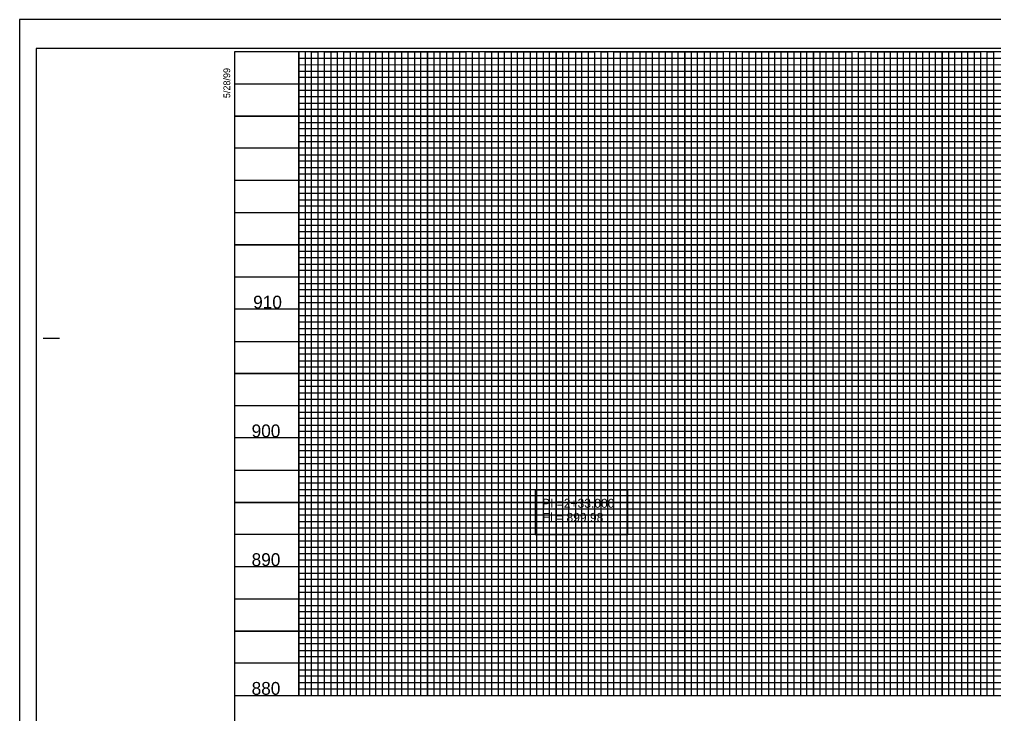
# Model space of a CAD drawing. Extents: x 1648435 to 1651603, y 802691 to 845762.
# Drawn here: x 1648862 to 1649619, y 803252 to 803791 of the extents above; entities that cross this region are included whole.
import ezdxf

# ---------------------------------------------------------------- set-up
doc = ezdxf.new("R2010")
doc.units = 0
for name, color, linetype in [('Exist Vertical Profile Vertical Axis Label', 7, 'Continuous'), ('Prop Grid Mask', 7, 'Continuous'), ('Prop VPI Ditch Grade Right Label', 7, 'Continuous'), ('Sheet Cutting Line CELL', 7, 'Continuous'), ('Sheet DOT Grid CELL', 7, 'Continuous'), ('Sheet Layout Profile Border Port 1', 7, 'Continuous'), ('Sheet Plot Border Inside CELL', 7, 'Continuous'), ('Sheet Plot Border Outside CELL', 7, 'Continuous'), ('Sheet Profile CELL', 7, 'Continuous'), ('Sheet Profile Grid Major CELL', 7, 'Continuous'), ('Sheet Profile Grid Middle CELL', 7, 'Continuous'), ('Sheet Profile Grid Minor CELL', 7, 'Continuous')]:
    doc.layers.add(name, color=color, linetype=linetype)

msp = doc.modelspace()

# ---------------------------------------------------------------- linework, layer by layer
at = {"layer": 'Prop Grid Mask'}
msp.add_lwpolyline([(1649263.05, 803425.57), (1649263.05, 803391.16), (1649335.02, 803391.16), (1649335.02, 803425.57)], close=True, dxfattribs=at)
at = {"layer": 'Sheet Cutting Line CELL'}
for p, q in [((1650546.28, 803791.02), (1648862.28, 803791.02)), ((1648862.28, 803791.02), (1648862.28, 802691.02))]:
    msp.add_line(p, q, dxfattribs=at)
at = {"layer": 'Sheet DOT Grid CELL'}
for p, q in [((1649079.28, 803266.02), (1649079.28, 803766.02)), ((1649129.28, 803266.02), (1649129.28, 803766.02)), ((1649179.28, 803266.02), (1649179.28, 803766.02)), ((1649229.28, 803266.02), (1649229.28, 803766.02)), ((1649279.28, 803266.02), (1649279.28, 803766.02)), ((1649329.28, 803266.02), (1649329.28, 803766.02)), ((1649379.28, 803266.02), (1649379.28, 803766.02)), ((1649429.28, 803266.02), (1649429.28, 803766.02)), ((1649479.28, 803266.02), (1649479.28, 803766.02)), ((1649529.28, 803266.02), (1649529.28, 803766.02)), ((1649579.28, 803266.02), (1649579.28, 803766.02)), ((1650329.23, 803716.02), (1649029.28, 803716.02)), ((1650329.23, 803666.02), (1649029.28, 803666.02)), ((1650329.28, 803616.02), (1649029.28, 803616.02)), ((1650529.28, 803566.02), (1649029.28, 803566.02)), ((1650529.28, 803516.02), (1649029.28, 803516.02)), ((1650529.28, 803466.02), (1649029.28, 803466.02)), ((1650529.28, 803416.02), (1649029.28, 803416.02)), ((1650529.28, 803366.02), (1649029.28, 803366.02)), ((1650529.28, 803316.02), (1649029.28, 803316.02))]:
    msp.add_line(p, q, dxfattribs=at)
at = {"layer": 'Sheet Layout Profile Border Port 1'}
msp.add_lwpolyline([(1649079.28, 803604.97), (1649079.28, 803266.02), (1650479.28, 803266.02), (1650479.28, 803604.97)], dxfattribs=at)
at = {"layer": 'Sheet Plot Border Inside CELL'}
msp.add_lwpolyline([(1648875.28, 802713.47), (1650541.78, 802713.47), (1650541.78, 803768.57), (1648875.28, 803768.57)], close=True, dxfattribs=at)
at = {"layer": 'Sheet Plot Border Outside CELL'}
msp.add_lwpolyline([(1648862.28, 802691.02), (1650546.28, 802691.02), (1650546.28, 803791.02), (1648862.28, 803791.02)], close=True, dxfattribs=at)
at = {"layer": 'Sheet Profile CELL'}
for p, q in [((1648880.78, 803543.52), (1648893.28, 803543.52)), ((1649029.28, 803266.02), (1650529.28, 803266.02))]:
    msp.add_line(p, q, dxfattribs=at)
msp.add_lwpolyline([(1650529.28, 803766.02), (1649029.28, 803766.02), (1649029.28, 802716.02), (1650529.28, 802716.02)], close=True, dxfattribs=at)
at = {"layer": 'Sheet Profile Grid Major CELL'}
for points in [[(1649079.28, 803766.02), (1649079.28, 803266.02), (1649129.28, 803266.02), (1649129.28, 803766.02), (1649179.28, 803766.02), (1649179.28, 803266.02), (1649229.28, 803266.02), (1649229.28, 803766.02), (1649279.28, 803766.02), (1649279.28, 803266.02), (1649329.28, 803266.02), (1649329.28, 803766.02), (1649379.28, 803766.02), (1649379.28, 803266.02), (1649429.28, 803266.02), (1649429.28, 803766.02), (1649479.28, 803766.02), (1649479.28, 803266.02), (1649529.28, 803266.02), (1649529.28, 803766.02), (1649579.28, 803766.02), (1649579.28, 803266.02), (1649629.28, 803266.02)], [(1649029.28, 803716.02), (1650329.28, 803716.02)], [(1650329.28, 803666.02), (1649029.28, 803666.02), (1649029.28, 803616.02), (1650329.28, 803616.02)], [(1650529.28, 803566.02), (1649029.28, 803566.02), (1649029.28, 803516.02), (1650529.28, 803516.02)], [(1650529.28, 803466.02), (1649029.28, 803466.02), (1649029.28, 803416.02), (1650529.28, 803416.02)], [(1650529.28, 803366.02), (1649029.28, 803366.02), (1649029.28, 803366.02), (1649029.28, 803316.02), (1650529.28, 803316.02)]]:
    msp.add_lwpolyline(points, dxfattribs=at)
at = {"layer": 'Sheet Profile Grid Middle CELL'}
msp.add_line((1649029.28, 803741.02), (1650179.28, 803741.02), dxfattribs=at)
for points in [[(1649104.28, 803766.02), (1649104.28, 803266.02), (1649154.28, 803266.02), (1649154.28, 803766.02), (1649204.28, 803766.02), (1649204.28, 803266.02), (1649254.28, 803266.02), (1649254.28, 803766.02), (1649304.28, 803766.02), (1649304.28, 803266.02), (1649354.28, 803266.02), (1649354.28, 803766.02), (1649404.28, 803766.02), (1649404.28, 803266.02), (1649454.28, 803266.02), (1649454.28, 803766.02), (1649504.28, 803766.02), (1649504.28, 803266.02), (1649554.28, 803266.02), (1649554.28, 803766.02), (1649604.28, 803766.02), (1649604.28, 803266.02), (1649654.28, 803266.02)], [(1650329.28, 803691.02), (1649029.28, 803691.02), (1649029.28, 803641.02), (1650329.28, 803641.02)], [(1650529.28, 803591.02), (1649029.28, 803591.02), (1649029.28, 803541.02), (1650354.28, 803541.02)], [(1650529.28, 803491.02), (1649029.28, 803491.02), (1649029.28, 803441.02), (1650529.28, 803441.02)], [(1650529.28, 803391.02), (1649029.28, 803391.02), (1649029.28, 803341.02), (1650529.28, 803341.02)], [(1650529.28, 803291.02), (1649029.28, 803291.02)]]:
    msp.add_lwpolyline(points, dxfattribs=at)
at = {"layer": 'Sheet Profile Grid Minor CELL'}
for p, q in [((1649079.28, 803761.02), (1650037.42, 803761.02)), ((1649079.28, 803761.02), (1650179.28, 803761.02)), ((1649079.28, 803756.02), (1649079.28, 803756.02)), ((1649079.28, 803756.02), (1649079.28, 803756.02)), ((1649079.28, 803756.02), (1649079.28, 803756.02)), ((1649079.28, 803756.02), (1649079.28, 803756.02)), ((1650179.28, 803755.98), (1649079.28, 803755.67)), ((1649079.28, 803751.02), (1650179.28, 803751.02)), ((1650329.23, 803631.02), (1649079.28, 803631.02)), ((1650329.28, 803626.02), (1649079.28, 803626.02)), ((1650329.28, 803621.02), (1649079.28, 803621.02)), ((1649079.28, 803611.02), (1650329.28, 803611.02)), ((1650329.28, 803606.02), (1649079.28, 803606.02)), ((1649079.28, 803601.02), (1650479.28, 803601.02)), ((1650479.28, 803581.02), (1649079.28, 803581.02)), ((1649079.28, 803576.02), (1650479.28, 803576.02)), ((1650479.28, 803556.02), (1649079.28, 803556.02)), ((1649079.28, 803551.02), (1650479.28, 803551.02)), ((1650479.28, 803531.02), (1649079.28, 803531.02)), ((1649079.28, 803526.02), (1650479.28, 803526.02)), ((1650479.28, 803521.02), (1649079.28, 803521.02)), ((1649079.28, 803511.02), (1650479.28, 803511.02)), ((1650479.28, 803506.02), (1649079.28, 803506.02)), ((1649079.28, 803501.02), (1650479.28, 803501.02)), ((1650479.28, 803496.02), (1649079.28, 803496.02)), ((1649079.28, 803486.02), (1650479.28, 803486.02)), ((1650479.28, 803481.02), (1649079.28, 803481.02)), ((1649079.28, 803476.02), (1650479.28, 803476.02)), ((1650479.28, 803471.02), (1649079.28, 803471.02)), ((1649079.28, 803461.02), (1650479.28, 803461.02)), ((1650479.28, 803456.02), (1649079.28, 803456.02)), ((1649079.28, 803451.02), (1650479.28, 803451.02)), ((1650479.28, 803446.02), (1649079.28, 803446.02)), ((1649079.28, 803436.02), (1650479.28, 803436.02)), ((1650479.28, 803431.02), (1649079.28, 803431.02)), ((1649079.28, 803426.02), (1650479.28, 803426.02)), ((1650479.28, 803421.02), (1649079.28, 803421.02)), ((1649079.28, 803411.02), (1650479.28, 803411.02)), ((1650479.28, 803406.02), (1649079.28, 803406.02)), ((1649079.28, 803401.02), (1650479.28, 803401.02)), ((1650479.28, 803396.02), (1649079.28, 803396.02)), ((1649079.28, 803386.02), (1650479.28, 803386.02)), ((1650479.28, 803381.02), (1649079.28, 803381.02)), ((1650479.28, 803376.02), (1649079.28, 803376.02)), ((1650479.28, 803371.02), (1649079.28, 803371.02)), ((1649079.28, 803361.02), (1650479.28, 803361.02)), ((1650479.28, 803356.02), (1649079.28, 803356.02)), ((1649079.28, 803351.02), (1650479.28, 803351.02)), ((1650479.28, 803346.02), (1649079.28, 803346.02)), ((1649079.28, 803336.02), (1650479.28, 803336.02)), ((1650479.28, 803331.02), (1649079.28, 803331.02)), ((1649079.28, 803326.02), (1650479.28, 803326.02)), ((1650479.28, 803321.02), (1649079.28, 803321.02)), ((1649079.28, 803311.02), (1650479.28, 803311.02)), ((1650479.28, 803306.02), (1649079.28, 803306.02)), ((1649079.28, 803301.02), (1650479.28, 803301.02)), ((1650479.28, 803296.02), (1649079.28, 803296.02)), ((1649079.28, 803286.02), (1650479.28, 803286.02)), ((1650479.28, 803281.02), (1649079.28, 803281.02)), ((1649079.28, 803276.02), (1650479.28, 803276.02))]:
    msp.add_line(p, q, dxfattribs=at)
for points in [[(1649084.28, 803766.02), (1649084.28, 803266.02), (1649089.28, 803266.02), (1649089.28, 803766.02), (1649094.28, 803766.02), (1649094.28, 803266.02), (1649099.28, 803266.02), (1649099.28, 803766.02), (1649109.28, 803766.02), (1649109.28, 803266.02), (1649114.28, 803266.02), (1649114.28, 803766.02), (1649119.28, 803766.02), (1649119.28, 803266.02), (1649124.28, 803266.02), (1649134.28, 803266.02), (1649139.28, 803266.02), (1649139.28, 803766.02), (1649144.28, 803766.02), (1649144.28, 803266.02), (1649149.28, 803266.02), (1649149.28, 803766.02), (1649159.28, 803766.02), (1649159.28, 803266.02), (1649164.28, 803266.02), (1649164.28, 803766.02), (1649169.28, 803766.02), (1649169.28, 803266.02), (1649174.28, 803266.02), (1649174.28, 803766.02), (1649184.28, 803766.02), (1649184.28, 803266.02), (1649189.28, 803266.02), (1649189.28, 803766.02), (1649194.28, 803766.02), (1649194.28, 803266.02), (1649199.28, 803266.02), (1649199.28, 803766.02), (1649209.28, 803766.02), (1649209.28, 803266.02), (1649214.28, 803266.02), (1649214.28, 803766.02), (1649219.28, 803766.02), (1649219.28, 803266.02), (1649224.28, 803266.02), (1649224.28, 803766.02), (1649234.28, 803766.02), (1649234.28, 803266.02), (1649239.28, 803266.02), (1649239.28, 803766.02), (1649244.28, 803766.02), (1649244.28, 803266.02), (1649249.28, 803266.02), (1649249.28, 803766.02), (1649259.28, 803766.02), (1649259.28, 803266.02), (1649264.28, 803266.02), (1649264.28, 803766.02), (1649269.28, 803766.02), (1649269.28, 803266.02), (1649274.28, 803266.02), (1649274.28, 803766.02), (1649284.28, 803766.02), (1649284.28, 803266.02), (1649289.28, 803266.02), (1649289.28, 803766.02), (1649294.28, 803766.02), (1649294.28, 803266.02)], [(1649124.28, 803266.02), (1649124.28, 803766.02), (1649134.28, 803766.02), (1649134.28, 803266.02)], [(1649294.28, 803266.02), (1649299.28, 803266.02), (1649299.28, 803766.02), (1649309.28, 803766.02), (1649309.28, 803266.02), (1649314.28, 803266.02), (1649314.28, 803766.02), (1649319.28, 803766.02), (1649319.28, 803266.02), (1649324.28, 803266.02), (1649324.28, 803766.02), (1649334.28, 803766.02), (1649334.28, 803266.02), (1649339.28, 803266.02), (1649339.28, 803766.02), (1649344.28, 803766.02), (1649344.28, 803266.02), (1649349.28, 803266.02), (1649349.28, 803766.02), (1649359.28, 803766.02), (1649359.28, 803266.02), (1649364.28, 803266.02), (1649364.28, 803766.02), (1649369.28, 803766.02), (1649369.28, 803266.02), (1649374.28, 803266.02), (1649374.28, 803766.02), (1649384.28, 803766.02), (1649384.28, 803266.02), (1649389.28, 803266.02), (1649389.28, 803766.02), (1649394.28, 803766.02), (1649394.28, 803266.02), (1649399.28, 803266.02), (1649399.28, 803766.02), (1649409.28, 803766.02), (1649409.28, 803266.02), (1649414.28, 803266.02), (1649414.28, 803766.02), (1649419.28, 803766.02), (1649419.28, 803266.02), (1649424.28, 803266.02), (1649424.28, 803766.02), (1649434.28, 803766.02), (1649434.28, 803266.02), (1649439.28, 803266.02), (1649439.28, 803766.02), (1649444.28, 803766.02), (1649444.28, 803266.02), (1649449.28, 803266.02), (1649449.28, 803766.02), (1649459.28, 803766.02), (1649459.28, 803266.02), (1649464.28, 803266.02), (1649464.28, 803766.02), (1649469.28, 803766.02), (1649469.28, 803266.02), (1649474.28, 803266.02), (1649474.28, 803766.02), (1649484.28, 803766.02), (1649484.28, 803266.02), (1649489.28, 803266.02), (1649489.28, 803766.02), (1649494.28, 803766.02), (1649494.28, 803266.02), (1649499.28, 803266.02), (1649499.28, 803766.02), (1649509.28, 803766.02), (1649509.28, 803266.02), (1649514.28, 803266.02), (1649514.28, 803766.02), (1649519.28, 803766.02), (1649519.28, 803266.02), (1649524.28, 803266.02), (1649524.28, 803766.02), (1649534.28, 803766.02), (1649534.28, 803266.02), (1649539.28, 803266.02), (1649539.28, 803766.02), (1649544.28, 803766.02), (1649544.28, 803266.02), (1649549.28, 803266.02), (1649549.28, 803766.02), (1649559.28, 803766.02), (1649559.28, 803266.02), (1649564.28, 803266.02), (1649564.28, 803766.02), (1649569.28, 803766.02), (1649569.28, 803266.02), (1649574.28, 803266.02), (1649574.28, 803766.02), (1649584.28, 803766.02), (1649584.28, 803266.02), (1649589.28, 803266.02), (1649589.28, 803766.02), (1649594.28, 803766.02), (1649594.28, 803266.02), (1649599.28, 803266.02), (1649599.28, 803766.02), (1649609.28, 803766.02)], [(1649609.28, 803766.02), (1649609.28, 803266.02), (1649614.28, 803266.02), (1649614.28, 803766.02), (1649619.28, 803766.02), (1649619.28, 803266.02), (1649624.28, 803266.02)], [(1650179.28, 803746.02), (1649079.28, 803746.02), (1649079.28, 803736.02), (1650329.28, 803736.02)], [(1650329.23, 803731.02), (1649079.28, 803731.02), (1649079.28, 803726.02), (1650329.28, 803726.02)], [(1650329.28, 803721.02), (1649079.28, 803721.02), (1649079.28, 803711.02), (1650329.28, 803711.02)], [(1650329.28, 803706.02), (1649079.28, 803706.02), (1649079.28, 803701.02), (1650329.28, 803701.02)], [(1650329.28, 803696.02), (1649079.28, 803696.02), (1649079.28, 803686.02), (1650329.28, 803686.02)], [(1650329.28, 803681.02), (1649079.28, 803681.02), (1649079.28, 803676.02), (1650329.28, 803676.02)], [(1650329.28, 803671.02), (1649079.28, 803671.02), (1649079.28, 803661.02), (1650329.28, 803661.02)], [(1650329.28, 803655.92), (1649079.38, 803655.92), (1649079.38, 803651.02), (1650329.28, 803651.02)], [(1650329.28, 803646.02), (1649079.28, 803646.02), (1649079.28, 803636.02), (1650329.28, 803636.02)], [(1650479.28, 803596.02), (1649079.28, 803596.02), (1649079.28, 803586.02), (1650479.28, 803586.02)], [(1650479.28, 803571.02), (1649079.28, 803571.02), (1649079.28, 803561.02), (1650479.28, 803561.02)], [(1650479.28, 803546.02), (1649079.28, 803546.02), (1649079.28, 803536.02), (1650479.28, 803536.02)], [(1650479.28, 803271.02), (1649079.28, 803271.02)]]:
    msp.add_lwpolyline(points, dxfattribs=at)

# ---------------------------------------------------------------- texts
at = {"layer": 'Exist Vertical Profile Vertical Axis Label'}
for s, p in [('910', (1649043.91, 803566.52)), ('900', (1649042.71, 803466.52)), ('890', (1649042.71, 803366.52)), ('880', (1649042.71, 803266.52))]:
    msp.add_text(s, height=10, dxfattribs=at).set_placement(p)
at = {"layer": 'Prop VPI Ditch Grade Right Label'}
for s, p in [('PI =2+33.000', (1649268.42, 803411.79)), ('El = 899.98', (1649268.42, 803400.79))]:
    msp.add_text(s, height=7, dxfattribs=at).set_placement(p)
at = {"layer": 'Sheet Profile CELL'}
msp.add_text('5/28/99', height=5.25, rotation=90, dxfattribs=at).set_placement((1649026.04, 803729.94))

doc.saveas('drawing.dxf')
